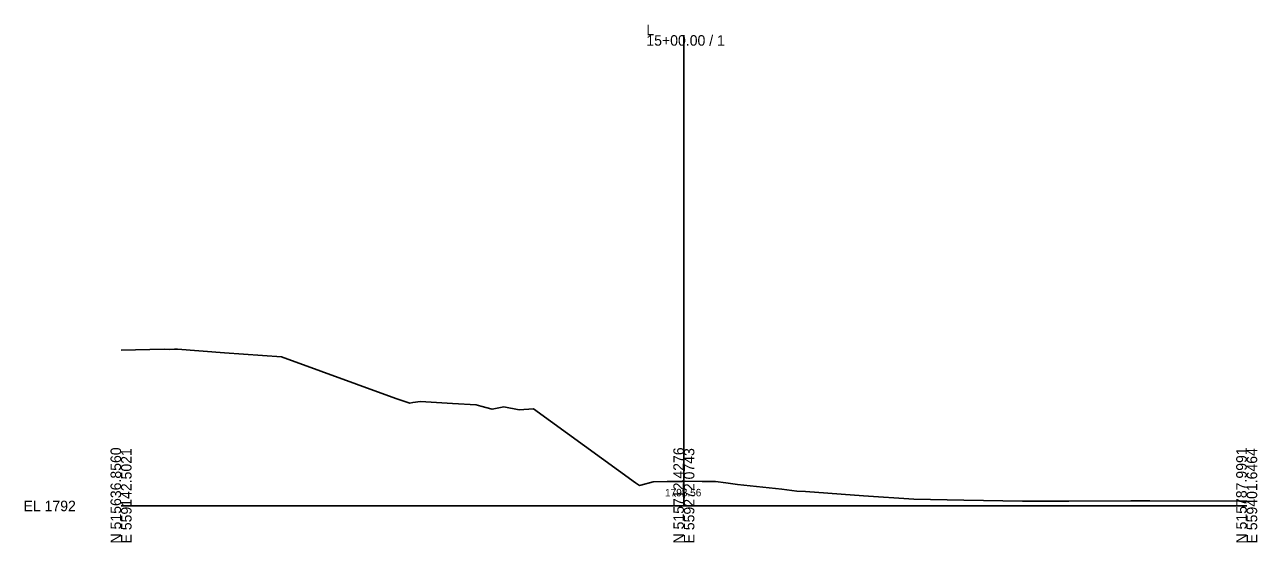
# Model space of a CAD drawing. Extents: x -26 to 1303, y -10 to 9545.
# Drawn here: x 974.3 to 1302.8, y 3490.3 to 3628.2 of the extents above; entities that cross this region are included whole.
import ezdxf

# ---------------------------------------------------------------- set-up
doc = ezdxf.new("R2010")
doc.units = 0
for name, color, linetype in [('Exist Cross Section Cell', 7, 'Continuous'), ('Exist XS Center Line Elevation Label', 7, 'Continuous'), ('Exist XS Ground Line', 7, 'Continuous')]:
    doc.layers.add(name, color=color, linetype=linetype)

msp = doc.modelspace()

# ---------------------------------------------------------------- linework, layer by layer
at = {"layer": 'Exist Cross Section Cell'}
for p, q in [((1150, 3500), (1150, 3625.43)), ((1000, 3500), (1150, 3500)), ((1150, 3500), (1300, 3500))]:
    msp.add_line(p, q, dxfattribs=at)
at = {"layer": 'Exist XS Ground Line'}
for p, q in [((1000, 3541.5), (1011.49, 3541.76)), ((1011.49, 3541.76), (1012.81, 3541.71)), ((1012.81, 3541.71), (1014.22, 3541.81)), ((1014.22, 3541.81), (1015.04, 3541.78)), ((1015.04, 3541.78), (1027.6, 3540.79)), ((1027.6, 3540.79), (1042.77, 3539.74)), ((1042.77, 3539.74), (1073.25, 3528.65)), ((1073.25, 3528.65), (1076.93, 3527.4)), ((1076.93, 3527.4), (1077.72, 3527.55)), ((1077.72, 3527.55), (1079.83, 3527.87)), ((1079.83, 3527.87), (1088.36, 3527.34)), ((1088.36, 3527.34), (1094.67, 3526.93)), ((1094.67, 3526.93), (1095.9, 3526.56)), ((1095.9, 3526.56), (1098.95, 3525.82)), ((1098.95, 3525.82), (1102.06, 3526.4)), ((1102.06, 3526.4), (1106.06, 3525.6)), ((1106.06, 3525.6), (1109.96, 3525.84)), ((1109.96, 3525.84), (1137.08, 3506.13)), ((1137.08, 3506.13), (1138.16, 3505.41)), ((1138.16, 3505.41), (1138.51, 3505.5)), ((1138.51, 3505.5), (1141.83, 3506.43)), ((1141.83, 3506.43), (1145.55, 3506.48)), ((1145.55, 3506.48), (1150, 3506.56)), ((1150, 3506.56), (1150.4, 3506.57)), ((1150.4, 3506.57), (1154.89, 3506.54)), ((1154.89, 3506.54), (1158.42, 3506.51)), ((1158.42, 3506.51), (1161.18, 3506.2)), ((1161.18, 3506.2), (1164.32, 3505.74)), ((1164.32, 3505.74), (1176.14, 3504.47)), ((1176.14, 3504.47), (1180.07, 3503.97)), ((1180.07, 3503.97), (1182.38, 3503.81)), ((1182.38, 3503.81), (1197.87, 3502.68)), ((1197.87, 3502.68), (1211.25, 3501.82)), ((1211.25, 3501.82), (1224.65, 3501.54)), ((1224.65, 3501.54), (1240.21, 3501.29)), ((1240.21, 3501.29), (1252.63, 3501.27)), ((1252.63, 3501.27), (1269.15, 3501.33)), ((1269.15, 3501.33), (1274.2, 3501.39)), ((1274.2, 3501.39), (1298.09, 3501.31)), ((1298.09, 3501.31), (1300, 3501.31))]:
    msp.add_line(p, q, dxfattribs=at)

# ---------------------------------------------------------------- texts
at = {"layer": 'Exist Cross Section Cell'}
for s, p in [('L', (1140, 3625.43)), ('15+00.00 / 1', (1140, 3622.63)), ('EL 1792', (974, 3498.6))]:
    msp.add_text(s, height=2.8, dxfattribs=at).set_placement(p)
for s, p in [('N 515636.8560', (1000, 3490)), ('N 515712.4276', (1150, 3490)), ('N 515787.9991', (1300, 3490)), ('E 559142.5021', (1002.8, 3490)), ('E 559272.0743', (1152.8, 3490)), ('E 559401.6464', (1302.8, 3490))]:
    msp.add_text(s, height=2.8, rotation=90, dxfattribs=at).set_placement(p)
at = {"layer": 'Exist XS Center Line Elevation Label'}
msp.add_text('1798.56', height=2, dxfattribs=at).set_placement((1144.98, 3502.56))

doc.saveas('drawing.dxf')
